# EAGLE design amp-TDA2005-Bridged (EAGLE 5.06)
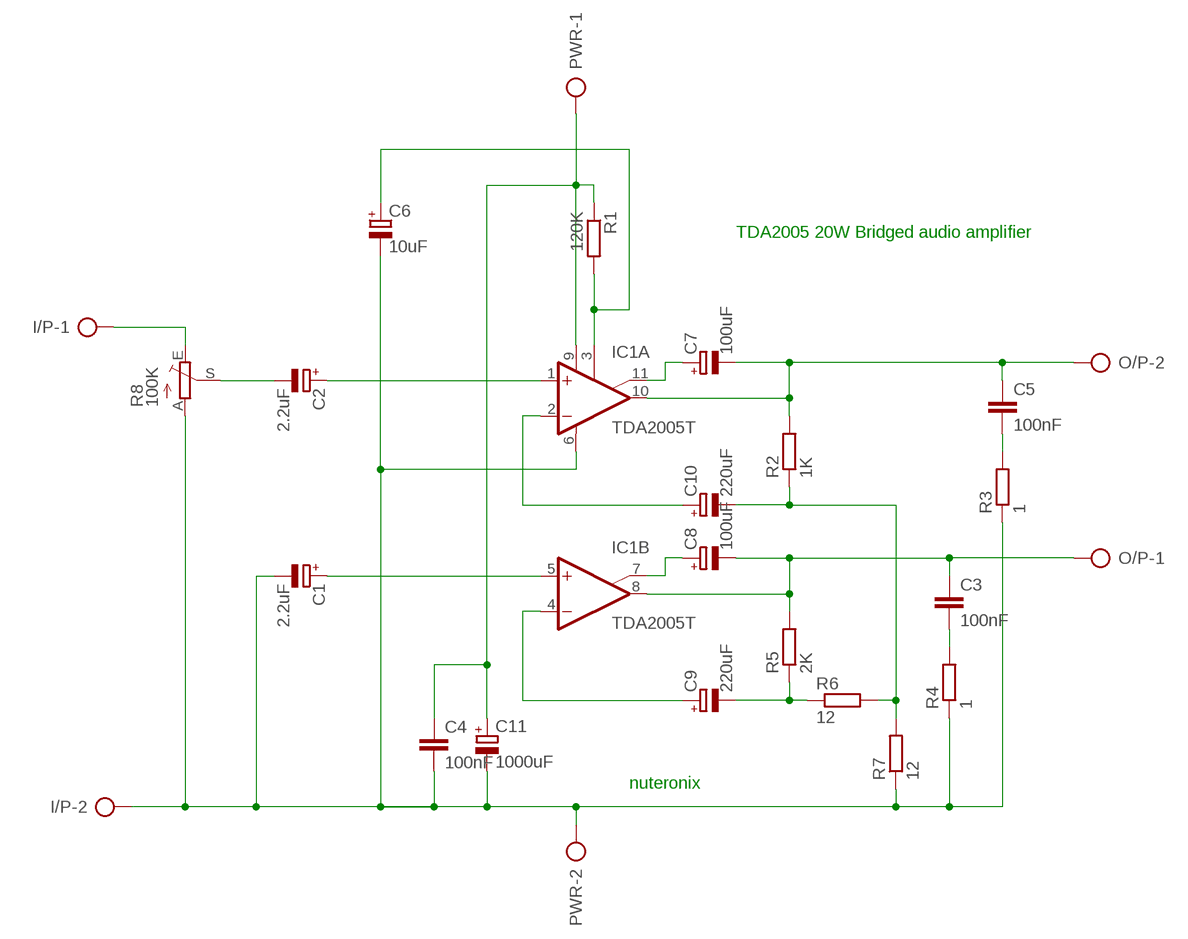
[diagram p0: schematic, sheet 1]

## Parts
C1  2.2uF  CPOL-EUE5-6  [E5-6]
C2  2.2uF  CPOL-EUE5-6  [E5-6]
C3  100nF  C-EU050-025X075  [C050-025X075]
C4  100nF  C-EU050-025X075  [C050-025X075]
C5  100nF  C-EU050-025X075  [C050-025X075]
C6  10uF  CPOL-EUE5-6  [E5-6]
C7  100uF  CPOL-EUE5-6  [E5-6]
C8  100uF  CPOL-EUE5-6  [E5-6]
C9  220uF  CPOL-EUE5-6  [E5-6]
C10  220uF  CPOL-EUE5-6  [E5-6]
C11  1000uF  CPOL-EUE5-8.5  [E5-8,5]
I/P  AK500/2  [AK500/2]
IC1  TDA2005T  [SIP11]
O/P  AK500/2  [AK500/2]
PWR  AK500/2  [AK500/2]
R1  120K  R-EU_0207/10  [0207/10]
R2  1K  R-EU_0207/10  [0207/10]
R3  1  R-EU_0207/10  [0207/10]
R4  1  R-EU_0207/10  [0207/10]
R5  2K  R-EU_0207/10  [0207/10]
R6  12  R-EU_0207/10  [0207/10]
R7  12  R-EU_0207/10  [0207/10]
R8  100K  TRIM_EU-ECP10P  [ECP10P]

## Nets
N$1: C2.+ IC1.1(A:+IN)
N$2: C1.+ IC1.5(B:+IN)
N$3: I/P.1 R8.E
N$4: C2.- R8.S
N$5: C3.1 C8.- IC1.8(B:OUT) O/P.1 R5.2
N$6: C6.+ IC1.3(A:SVRR) R1.2
N$7: C8.+ IC1.7(B:BTSP)
N$8: C10.+ IC1.2(A:-IN)
N$9: C7.+ IC1.11(A:BTSP)
N$10: C10.- R2.1 R6.2 R7.2
N$11: C5.2 R3.2
N$12: C5.1 C7.- IC1.10(A:OUT) O/P.2 R2.2
N$13: C9.+ IC1.4(B:-IN)
N$14: C9.- R5.1 R6.1
N$16: C3.2 R4.2
N$17: C1.- C4.2 C6.- C11.- I/P.2 IC1.6(A:GND) PWR.2 R3.1 R4.1 R7.1 R8.A
N$22: C4.1 C11.+ IC1.9(A:V+) PWR.1 R1.1

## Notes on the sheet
- TDA2005 20W Bridged audio amplifier
- nuteronix

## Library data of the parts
C1 C2 C6-C11 = rcl:CPOL-EU: POLARIZED CAPACITOR, European symbol
C3-C5 = rcl:C-EU: CAPACITOR, European symbol
I/P O/P PWR = con-ptr500:AK500/2: CONNECTOR
IC1 = linear:TDA2005: Power OP AMP
R1-R7 = rcl:R-EU_: RESISTOR, European symbol
R8 = pot:TRIM_EU-: POTENTIOMETER

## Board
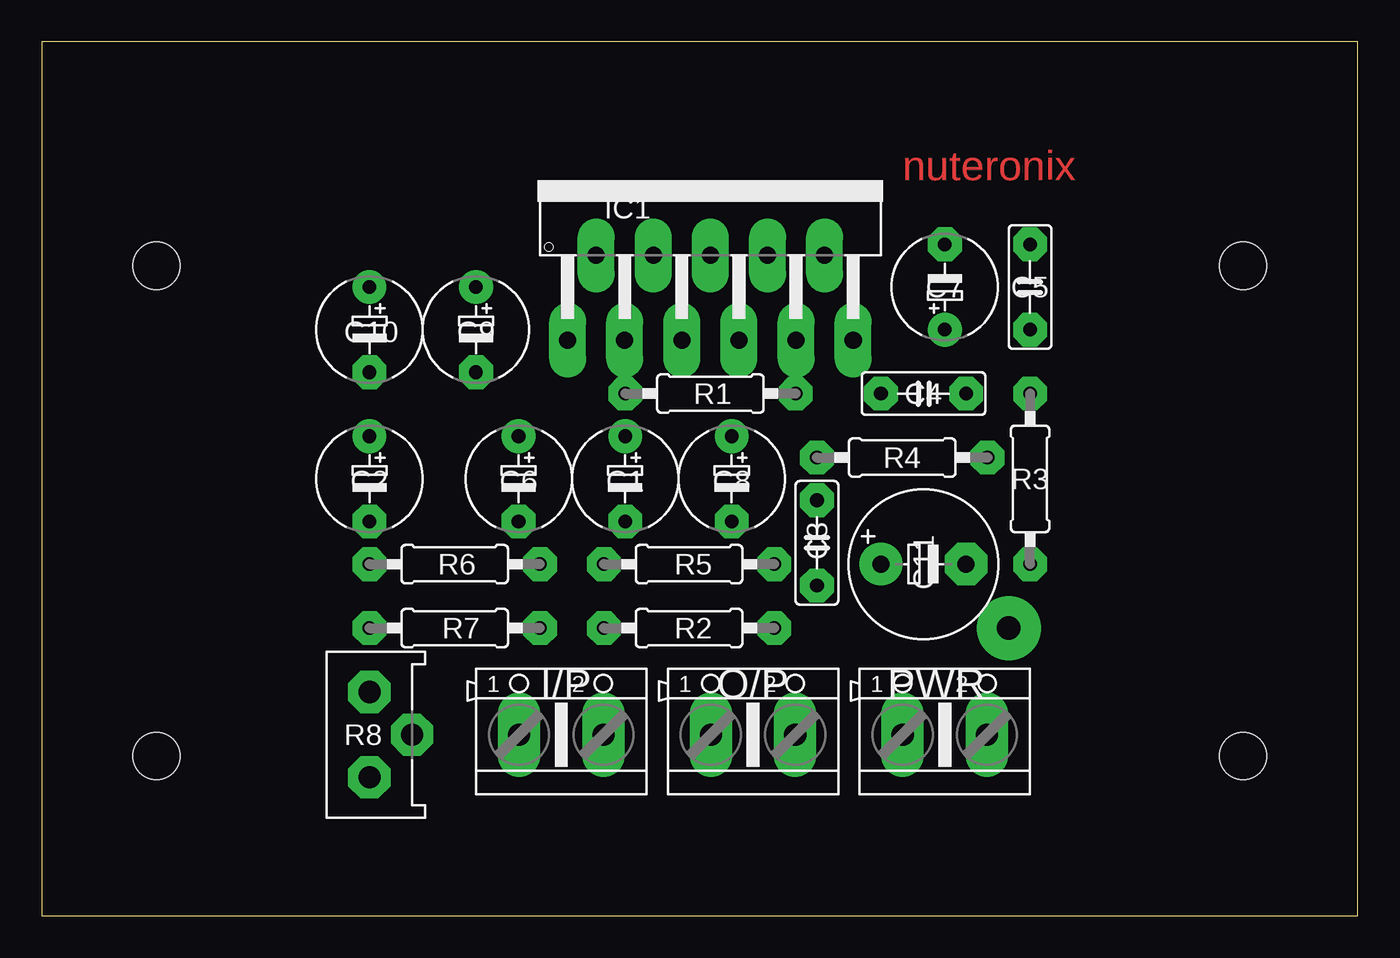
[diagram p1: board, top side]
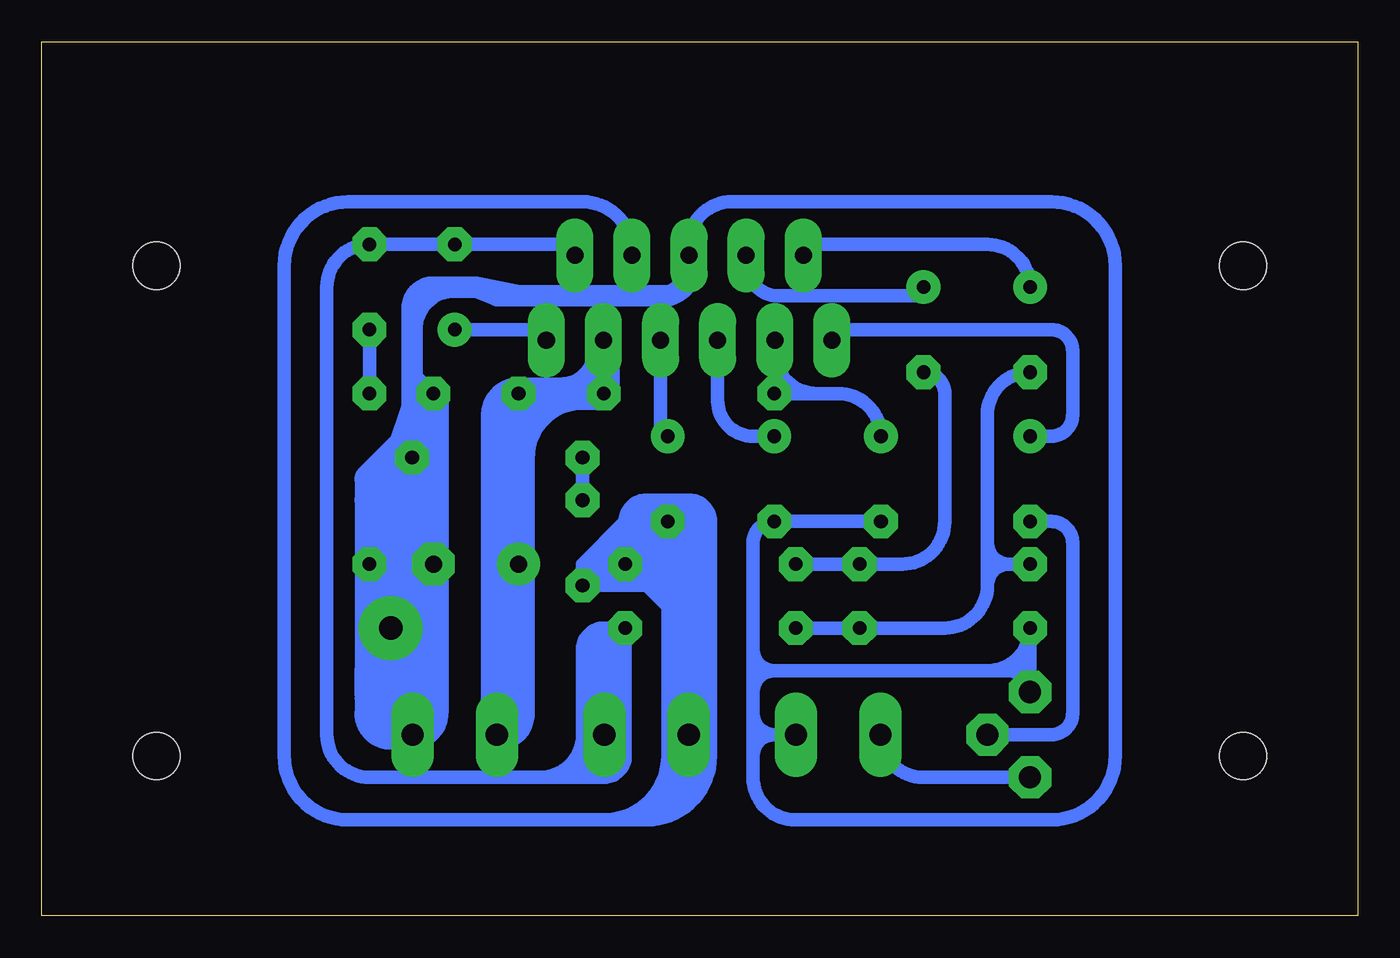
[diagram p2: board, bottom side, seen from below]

Size 78.41 x 52.06 mm. Coordinates in mm from the lower left corner, seen from the top.
Outline: 0,0 78.41,0 78.41,52.06 0,52.06 0,0
Copper layers (1*16): Top 0.035mm / dielectric 1.5mm / Bottom 0.035mm
Design rules "default": minimum track width 0.8mm, minimum drill 0.8mm, track to track 0.8mm, track to pad 0.8mm, pad to pad 8mil, via to via 0.8mm, smd to smd 8mil, copper to edge 40mil, drill to drill 8mil, minimum pad ring 0.6mm, minimum via ring 0.6mm, stop-mask expansion 4mil, vias tented up to drill 0mil, thermal gap 10mil
Holes 2.8 mm at 6.82,38.73 6.82,9.52 71.59,38.73 71.59,9.52

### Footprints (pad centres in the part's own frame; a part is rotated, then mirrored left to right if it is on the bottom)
E5-6 = drill 0.813 pad 1.905 round: + -2.54,0 | drill 0.813 pad 1.905 octagon: - 2.54,0
C050-025X075 = drill 0.813 octagon: 1 -2.54,0; 2 2.54,0
E5-8,5 = drill 1.016 pad 2.54 round: + -2.54,0 | drill 1.016 pad 2.54 octagon: - 2.54,0
AK500/2 = drill 1.321 long: 1 -2.515,0; 2 2.515,0
SIP11 = drill 1.016 long: 1 -8.509,-9.525; 2 -6.807,-4.47; 3 -5.105,-9.525; 4 -3.404,-4.47; 5 -1.702,-9.525; 6 0,-4.47; 7 1.702,-9.525; 8 3.404,-4.47; 9 5.105,-9.525; 10 6.807,-4.47; 11 8.509,-9.525
0207/10 = drill 0.813 octagon: 1 -5.08,0; 2 5.08,0
ECP10P = drill 1.321 octagon: A -2.54,0; E 2.54,0; S 0,2.54

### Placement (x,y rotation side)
C1  34.76,26.03 270 top
C2  19.52,26.03 270 top
C3  46.19,22.22 90 top
C4  52.54,31.11 0 top
C5  58.89,37.46 270 top
C6  28.41,26.03 270 top
C7  53.81,37.46 90 top
C8  41.11,26.03 270 top
C9  25.87,34.92 270 top
C10  19.52,34.92 270 top
C11  52.54,20.95 0 top
I/P  30.95,10.79 0 top
IC1  39.84,43.81 0 top
O/P  42.38,10.79 0 top
PWR  53.81,10.79 0 top
R1  39.84,31.11 180 top
R2  38.57,17.14 0 top
R3  58.89,26.03 90 top
R4  51.27,27.3 180 top
R5  38.57,20.95 0 top
R6  24.6,20.95 180 top
R7  24.6,17.14 0 top
R8  19.52,10.79 270 top

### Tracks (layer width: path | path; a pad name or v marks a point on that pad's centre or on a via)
N$1
  Bottom 0.813: C2.+ 18.25,28.57 arc-90 16.98,29.84 16.98,33.65 arc-90 18.25,34.92 30.7,34.92 arc-90 IC1.1
N$2
  Bottom 0.813: IC1.5 38.14,30.68 arc-90 36.03,28.57 C1.+
N$3
  Bottom 0.813: I/P.1 arc-90 25.89,8.25 R8.E
N$4
  Bottom 0.813: C2.- 18.25,23.49 arc90 16.98,22.22 16.98,12.06 arc90 18.25,10.79 R8.S
N$5
  Bottom 0.813: IC1.8 43.24,39.59 arc-90 46.19,42.54 60.16,42.54 arc-90 63.97,38.73 63.97,9.52 arc-90 60.16,5.71 46.19,5.71 | 46.19,20.95 C3.1 44.92,19.68 | 42.38,5.71 46.19,5.71 | 42.38,5.71 arc-90 38.57,9.52 38.57,23.49 arc-90 39.84,24.76 41.11,24.76 | 41.11,24.76 42.38,24.76 arc-90 43.65,23.49 | 46.19,5.71 44.92,5.71 arc-90 41.11,9.52 | 41.11,9.52 41.11,10.79 | 41.11,10.79 41.11,18.41 42.38,19.68 44.92,19.68 | 43.65,23.49 46.19,20.95 | C8.- 41.11,24.76 | 43.65,23.49 43.65,22.22 R5.2 | 41.11,10.79 O/P.1 | 41.11,6.98 41.11,9.52 | 41.11,6.98 42.38,5.71 | 41.11,6.98 39.84,8.25 | 41.11,6.98 39.84,9.52 39.84,6.98 | 39.84,6.98 41.11,6.98 | 39.84,6.98 42.38,5.71 | 44.92,19.68 46.19,20.95
  Bottom 1.778: 39.84,18.41 39.84,23.49 C8.- | 39.84,18.41 39.84,9.52 39.84,8.25 | C8.- 42.38,23.49 42.38,20.95 | 39.84,18.41 42.38,20.95 | C8.- 41.11,20.95 | 42.38,20.95 44.92,20.95 43.65,22.22
N$6
  Bottom 0.61: 33.49,31.11 arc90 34.76,32.38
  Bottom 0.813: C6.+ arc-90 30.95,31.11 32.22,31.11 | 32.22,31.11 33.49,31.11 R1.2 arc-90 34.73,31.13 IC1.3 | 32.22,31.11 arc90 34.76,33.65
N$7
  Bottom 0.813: IC1.7 41.54,29 arc-90 C8.+
N$8
  Bottom 0.813: C10.+ arc-90 22.06,40 32.37,40 arc-90 IC1.2
N$9
  Bottom 0.813: C7.+ 48.98,34.92 arc90 IC1.11
N$10
  Bottom 0.813: C10.- arc-90 22.06,29.84 22.06,22.22 | 22.06,19.68 arc90 24.6,17.14 R7.2 R2.1 | 20.79,20.95 arc90 22.06,22.22 | 22.06,22.22 22.06,19.68 | 20.79,20.95 arc-90 22.06,19.68 | R6.2 20.79,20.95
N$11
  Bottom 0.813: R3.2 C5.2
N$12
  Bottom 0.813: 48.73,8.25 58.89,8.25 arc90 61.43,10.79 61.43,37.46 arc90 C5.1 C7.- 47.31,40 arc90 IC1.10 | 44.92,8.25 46.19,8.25 | 46.19,8.25 47.46,8.25 | 47.46,8.25 48.73,8.25 | 44.92,8.25 arc-90 43.65,9.52 43.65,15.87 | 43.65,15.87 R2.2 44.92,17.14 | 44.92,17.14 arc-90 46.19,15.87 46.19,10.79 | 46.19,10.79 arc90 48.73,8.25 | 46.19,8.25 46.19,9.52 | 46.19,9.52 47.46,8.25 | 43.65,15.87 44.92,15.87 | 43.65,15.87 44.92,17.14 | 44.92,8.25 44.92,9.52 | 44.92,8.25 46.19,9.52 | 46.19,9.52 46.19,10.79
  Bottom 1.778: 44.92,10.79 O/P.2 | 44.92,10.79 44.92,15.87 | 44.92,9.52 44.92,10.79
N$13
  Bottom 0.813: IC1.4 36.44,39.14 arc-90 34.76,36.95 26.38,36.95 arc-90 C9.+
N$14
  Bottom 0.813: R5.1 R6.1 27.14,20.95 arc-90 24.6,23.49 24.6,31.11 arc-90 C9.-
N$15
  Bottom 1.27: 50,36.95 51.27,36.95
N$16
  Bottom 0.813: C3.2 R4.2
N$17
  Bottom 0.813: 34.76,10.79 33.49,10.79 | 36.03,8.25 36.03,9.52 arc90 34.76,10.79 | 36.03,8.25 arc-90 33.49,5.71 18.25,5.71 arc-90 14.44,9.52 14.44,38.73 arc-90 18.25,42.54 37.3,42.54 arc-90 39.84,40 IC1.6 39.84,38.73 | 19.52,14.6 R8.A arc-90 20.79,14.6 | 19.52,14.6 19.52,15.87 | 19.52,15.87 R7.1 arc90 22.06,14.6 | 22.06,14.6 20.79,14.6 | 20.79,14.6 19.52,14.6 | 20.79,14.6 19.52,15.87 | 34.76,14.6 22.06,14.6 | 36.03,15.87 arc-90 34.76,14.6 | 36.03,15.87 36.03,22.22 arc90 C1.- C6.- | 36.03,13.33 arc90 34.76,14.6 | 36.03,14.6 36.03,15.87 | 36.03,14.6 36.03,13.33 | 34.76,10.79 I/P.2 | 34.76,10.79 arc90 36.03,12.06 36.03,13.33 | 36.03,8.25 36.03,14.6 | 56.35,20.95 C11.- | R3.1 56.35,20.95 | 56.35,31.11 C4.2 56.35,32.38 | 56.35,31.11 56.35,29.84 56.35,28.57 R4.1 56.35,26.03 56.35,20.95 | 56.35,20.95 PWR.2 | 56.35,31.11 57.62,27.3 | 50,36.95 51.27,36.95
  Bottom 1.27: 55.08,37.46 arc-90 56.35,36.19 | 56.35,34.92 56.35,32.38 | 56.35,34.92 56.35,36.19 | 56.35,32.38 56.35,31.11 | 53.81,37.46 55.08,37.46 | 52.54,37.46 53.81,37.46 | 51.27,36.95 52.54,37.46 | 52.54,37.46 50,36.95 41.11,36.95 arc-90 39.84,38.73 39.84,40 | 56.35,32.38 56.35,29.84 | 55.08,37.46 56.35,36.19 | 53.81,37.46 arc-90 56.35,34.92
  Bottom 1.778: R4.1 arc-90 58.89,24.76 | 58.89,24.76 R3.1 58.89,14.6 | 58.89,14.6 58.89,13.33 arc-90 56.35,10.79 | 56.35,10.79 arc-90 55.08,12.06 55.08,27.3 | 55.08,27.3 56.35,28.57 57.62,27.3 58.89,26.03 58.89,24.76 | C4.2 55.08,27.3 | 56.35,10.79 57.62,10.79 | 57.62,10.79 arc90 58.89,12.06 58.89,14.6 | 56.35,10.79 56.35,26.03 arc-90 57.62,24.76 57.62,10.79
N$20  (via drill 1.4 pad 3.81)
  other vias: 57.62,17.14
N$22
  Bottom 1.93: IC1.9 44.95,31.13 arc-90 R1.1 | C4.1 48.73,31.11 | 48.73,31.11 47.46,31.11 | 47.46,31.11 R1.1 | 50,27.3 C11.+ 50,12.06 arc90 51.27,10.79 | 50,27.3 C4.1 | 51.27,10.79 PWR.1 | 51.27,10.79 51.27,28.57 | 51.27,28.57 arc90 48.73,31.11 | 51.27,28.57 51.27,29.84 arc90 C4.1 | 47.46,31.11 arc-90 44.92,33.65 | 50,27.3 arc90 46.19,31.11 R1.1

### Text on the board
Top: nuteronix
